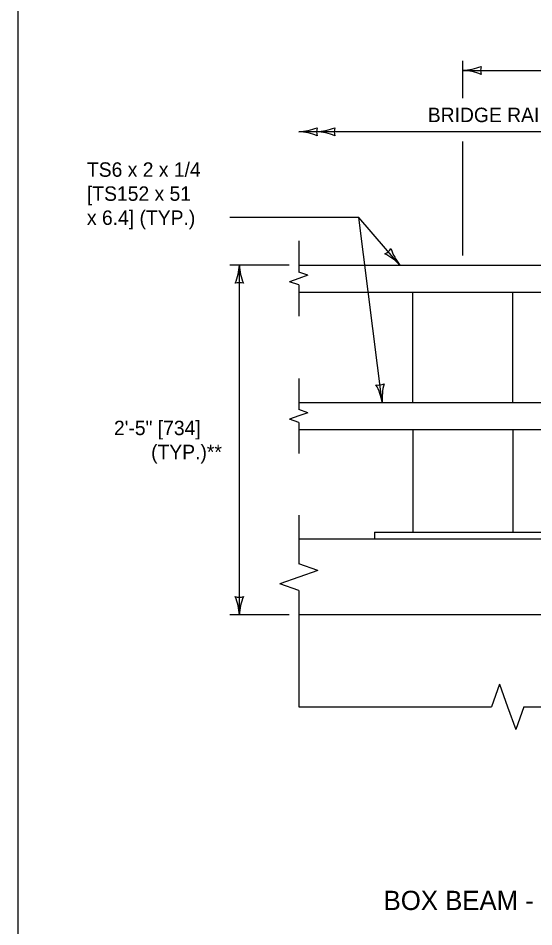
# Model space of a CAD drawing. Extents: x 49991.4 to 50021, y 49987.6 to 50011.4.
# Drawn here: x 49999.384 to 50001.527, y 49991.258 to 49995.037 of the extents above; entities that cross this region are included whole.
import ezdxf

# ---------------------------------------------------------------- set-up
doc = ezdxf.new("R2010")
doc.units = 0
for name, color, linetype in [('Level 1', 7, 'Continuous'), ('Level 2', 7, 'Continuous'), ('Level 3', 7, 'Continuous'), ('Level 6', 7, 'Continuous')]:
    doc.layers.add(name, color=color, linetype=linetype)

msp = doc.modelspace()

# ---------------------------------------------------------------- linework, layer by layer
at = {"layer": 'Level 1'}
for p, q in [((50000.5498, 49994.0102), (50001.4285, 49994.0102)), ((50001.4285, 49994.0102), (50002.2862, 49994.0102)), ((50000.5498, 49993.8979), (50001.3976, 49993.8979)), ((50001.0236, 49993.4389), (50001.0236, 49993.898)), ((50001.3976, 49993.8979), (50002.2862, 49993.8979)), ((50001.4401, 49993.4389), (50001.4401, 49993.898)), ((50000.5502, 49993.4387), (50002.2862, 49993.4387)), ((50000.5502, 49993.3264), (50002.2862, 49993.3264)), ((50001.0236, 49993.3264), (50001.0236, 49992.8992)), ((50001.4401, 49993.3264), (50001.4401, 49992.8992)), ((50000.8645, 49992.8993), (50001.5926, 49992.8993)), ((50000.8645, 49992.8992), (50000.8645, 49992.8695)), ((50002.2862, 49992.8695), (50000.5498, 49992.8695)), ((50002.0942, 49992.555), (50000.5502, 49992.555))]:
    msp.add_line(p, q, dxfattribs=at)
msp.add_lwpolyline([(49999.3835, 49998.9992), (50016.7501, 49998.9992), (50016.7501, 49987.7988), (49999.3835, 49987.7988)], close=True, dxfattribs=at)
at = {"layer": 'Level 3'}
for p, q in [((50001.2319, 49994.7046), (50001.2319, 49994.8597)), ((50001.2319, 49994.8197), (50003.6098, 49994.8197)), ((50002.2862, 49994.5646), (50000.5502, 49994.5646)), ((50001.2319, 49994.0502), (50001.2319, 49994.5246)), ((50000.7989, 49994.2072), (50000.2626, 49994.2072)), ((50000.8971, 49993.4387), (50000.7989, 49994.2072)), ((50000.9703, 49994.0102), (50000.7989, 49994.2072)), ((50000.5098, 49994.0102), (50000.2629, 49994.0102)), ((50000.3029, 49992.555), (50000.3029, 49994.0102)), ((50000.5102, 49992.555), (50000.2629, 49992.555))]:
    msp.add_line(p, q, dxfattribs=at)
for centre, radius, start, end in [((50001.2204, 49995.0524), 0.233, 272.8273, 292.0772), ((50001.2227, 49994.5976), 0.2223, 67.456, 87.6395), ((50001.3601, 49994.8197), 0.0548, 162.1388, 197.8612), ((50000.5387, 49994.7973), 0.233, 272.8273, 292.0772), ((50000.6121, 49994.7973), 0.233, 272.8273, 292.0772), ((50000.6784, 49994.5646), 0.0548, 162.1388, 197.8612), ((50000.7519, 49994.5646), 0.0548, 162.1388, 197.8612), ((50000.541, 49994.3425), 0.2223, 67.456, 87.6395), ((50000.6145, 49994.3425), 0.2223, 67.456, 87.6395), ((50000.8861, 49994.1069), 0.0548, 293.1532, 328.8756), ((50000.8022, 49993.8488), 0.233, 43.8417, 63.0915), ((50001.1439, 49994.1491), 0.2223, 198.4704, 218.6539), ((50000.0808, 49994.0194), 0.2223, 337.456, 357.6395), ((50000.5356, 49994.0217), 0.233, 182.8273, 202.0772), ((50000.3029, 49993.882), 0.0548, 72.1388, 107.8612), ((50000.8808, 49993.5659), 0.0548, 259.4161, 295.1384), ((50000.6677, 49993.3978), 0.233, 10.1045, 29.3544), ((50001.1186, 49993.4578), 0.2223, 164.7332, 184.9168), ((50000.3029, 49992.6832), 0.0548, 252.1388, 287.8612), ((50000.0702, 49992.5435), 0.233, 2.8273, 22.0772), ((50000.5251, 49992.5458), 0.2223, 157.456, 177.6395)]:
    msp.add_arc(centre, radius, start, end, dxfattribs=at)
at = {"layer": 'Level 6'}
for p, q in [((50000.5498, 49994.1102), (50000.5498, 49993.9808)), ((50000.5877, 49993.9675), (50000.5498, 49993.9808)), ((50000.5498, 49993.954), (50000.5119, 49993.9405)), ((50000.5498, 49993.9272), (50000.5119, 49993.9405)), ((50000.5877, 49993.9675), (50000.5498, 49993.954)), ((50000.5498, 49993.9272), (50000.5498, 49993.7979)), ((50000.5498, 49993.5387), (50000.5498, 49993.4093)), ((50000.5877, 49993.396), (50000.5498, 49993.4093)), ((50000.5498, 49993.3825), (50000.5119, 49993.369)), ((50000.5498, 49993.3557), (50000.5119, 49993.369)), ((50000.5877, 49993.396), (50000.5498, 49993.3825)), ((50000.5498, 49993.3557), (50000.5498, 49993.2264)), ((50000.5498, 49992.9695), (50000.5498, 49992.7679)), ((50000.6289, 49992.7401), (50000.5498, 49992.768)), ((50000.6289, 49992.7401), (50000.5498, 49992.7123)), ((50000.5498, 49992.7123), (50000.4708, 49992.684)), ((50000.5498, 49992.6561), (50000.4708, 49992.684)), ((50000.5498, 49992.6561), (50000.5498, 49992.1726)), ((50001.3848, 49992.2669), (50001.3516, 49992.1726)), ((50001.3848, 49992.2669), (50001.418, 49992.1726)), ((50000.5502, 49992.1726), (50001.3516, 49992.1726)), ((50001.418, 49992.1726), (50001.4518, 49992.0784)), ((50001.485, 49992.1726), (50001.4518, 49992.0784)), ((50001.485, 49992.1726), (50002.3862, 49992.1726))]:
    msp.add_line(p, q, dxfattribs=at)

# ---------------------------------------------------------------- texts
at = {"layer": 'Level 2'}
for s, height, p in [('BRIDGE RAIL**', 0.06, (50001.0861, 49994.6046)), ('TS6 x 2 x 1/4 ', 0.06, (49999.6693, 49994.3772)), ('[TS152 x 51', 0.06, (49999.6693, 49994.2772)), ('x 6.4] (TYP.)', 0.06, (49999.6693, 49994.1772)), ('2\'-5" [734]', 0.06, (49999.7817, 49993.3026)), ('(TYP.)**', 0.06, (49999.9361, 49993.2026)), ('BOX BEAM - BRIDGE APPROACH SECTION TYPE 1', 0.08, (50000.9026, 49991.3275))]:
    msp.add_text(s, height=height, dxfattribs=at).set_placement(p)

doc.saveas('drawing.dxf')
